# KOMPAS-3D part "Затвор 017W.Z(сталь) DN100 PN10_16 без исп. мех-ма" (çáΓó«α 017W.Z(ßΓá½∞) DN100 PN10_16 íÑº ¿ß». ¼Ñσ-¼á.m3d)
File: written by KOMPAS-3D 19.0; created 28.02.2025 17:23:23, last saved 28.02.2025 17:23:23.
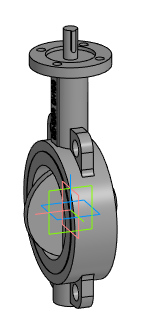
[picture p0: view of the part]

Document properties: Автор: Евгений; Полное имя файла: E:\Dendor Работа Сачек\3D для проекитирвщиков\1.5 Тип 017W.Z Сталь Затвор дисковый поворотный Межфланцевый\stp_Тип 017W.Z(сталь). Затвор без исполн. механизма\Затвор 017W.Z(сталь) DN100 PN10_16 без исп. мех-ма.m3d

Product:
- Part/product: Затвор 017W.Z(сталь) DN100 PN10_16 без исп. мех-ма

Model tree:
1. Операция без истории:1  (labels: Затвор 017W.Z(сталь) DN100 PN10_16 без исп. мех-ма)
